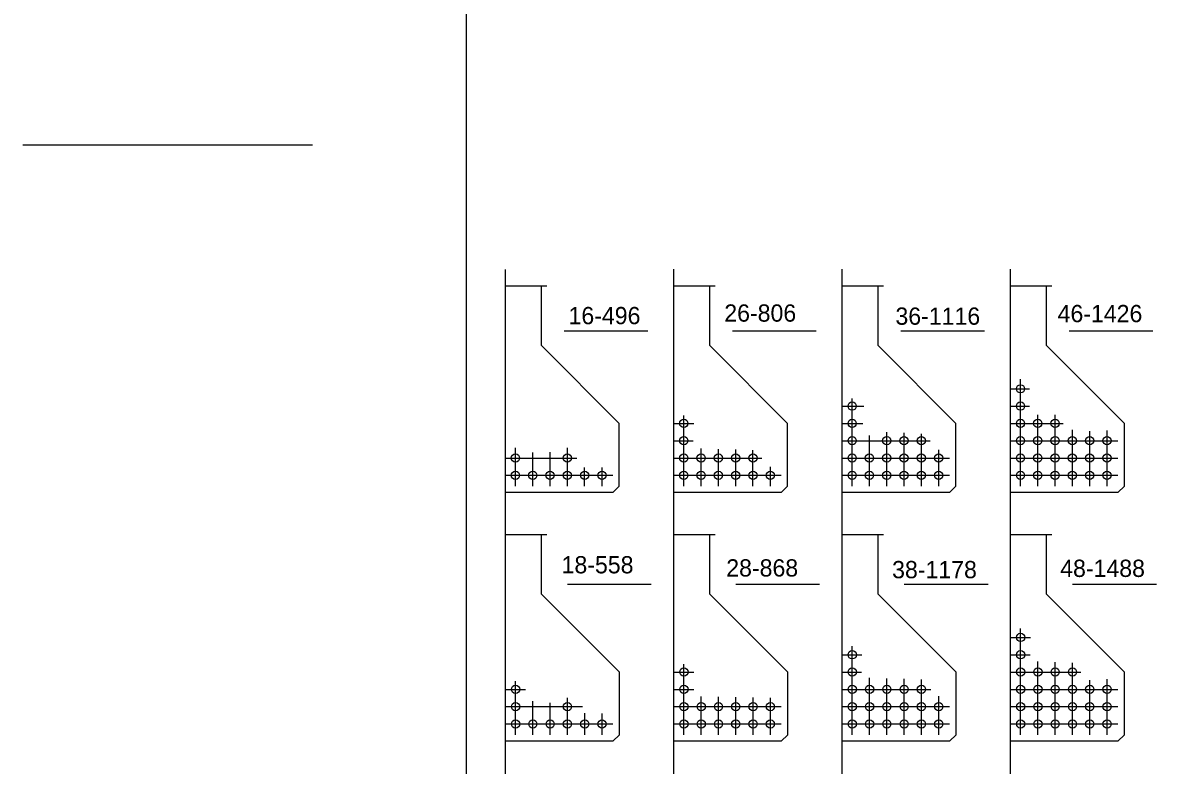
# Model space of a CAD drawing. Extents: x 1005 to 1123, y 2008 to 2074.
# Drawn here: x 1005.42 to 1027.31, y 2029.07 to 2043.4 of the extents above; entities that cross this region are included whole.
import ezdxf

# ---------------------------------------------------------------- set-up
doc = ezdxf.new("R2010")
doc.units = 0
for name, color, linetype in [('Level 1', 7, 'Continuous'), ('Level 37', 7, 'Continuous'), ('Level 8', 7, 'Continuous')]:
    doc.layers.add(name, color=color, linetype=linetype)

msp = doc.modelspace()

# ---------------------------------------------------------------- linework, layer by layer
at = {"layer": 'Level 1'}
msp.add_line((1013.989, 2013.041), (1013.989, 2069.04), dxfattribs=at)
at = {"layer": 'Level 37'}
msp.add_line((1011.017, 2041.04), (1005.42, 2041.04), dxfattribs=at)
at = {"layer": 'Level 8'}
for p, q in [((1014.732, 2038.643), (1014.739, 2014.968)), ((1017.982, 2038.644), (1017.989, 2014.969)), ((1021.232, 2038.645), (1021.239, 2014.97)), ((1024.482, 2038.646), (1024.489, 2014.971)), ((1014.731, 2038.326), (1015.539, 2038.326)), ((1014.767, 2038.326), (1015.539, 2038.326)), ((1015.434, 2037.172), (1015.434, 2038.326)), ((1017.981, 2038.326), (1018.789, 2038.326)), ((1018.017, 2038.326), (1018.789, 2038.326)), ((1018.684, 2037.172), (1018.684, 2038.326)), ((1021.231, 2038.326), (1022.039, 2038.326)), ((1021.267, 2038.326), (1022.039, 2038.326)), ((1021.934, 2037.172), (1021.934, 2038.326)), ((1024.481, 2038.326), (1025.289, 2038.326)), ((1024.517, 2038.326), (1025.289, 2038.326)), ((1025.184, 2037.172), (1025.184, 2038.326)), ((1015.871, 2037.454), (1017.487, 2037.454)), ((1019.121, 2037.454), (1020.737, 2037.454)), ((1019.121, 2037.454), (1020.737, 2037.454)), ((1022.371, 2037.454), (1023.987, 2037.454)), ((1022.371, 2037.454), (1023.987, 2037.454)), ((1022.371, 2037.454), (1023.987, 2037.454)), ((1025.621, 2037.454), (1027.237, 2037.454)), ((1025.621, 2037.454), (1027.237, 2037.454)), ((1025.621, 2037.454), (1027.237, 2037.454)), ((1025.621, 2037.454), (1027.237, 2037.454)), ((1016.938, 2035.669), (1015.434, 2037.172)), ((1020.188, 2035.669), (1018.684, 2037.172)), ((1023.438, 2035.669), (1021.934, 2037.172)), ((1026.688, 2035.669), (1025.184, 2037.172)), ((1024.683, 2034.458), (1024.683, 2036.522)), ((1024.482, 2036.337), (1024.86, 2036.337)), ((1021.433, 2034.458), (1021.433, 2036.149)), ((1021.232, 2036.003), (1021.657, 2036.003)), ((1024.482, 2036.003), (1024.86, 2036.003)), ((1025.018, 2034.458), (1025.018, 2035.836)), ((1025.351, 2034.458), (1025.351, 2035.836)), ((1016.938, 2034.458), (1016.938, 2035.669)), ((1017.982, 2035.669), (1018.377, 2035.669)), ((1018.183, 2034.458), (1018.183, 2035.823)), ((1020.188, 2034.458), (1020.188, 2035.669)), ((1021.232, 2035.669), (1021.641, 2035.669)), ((1023.438, 2034.458), (1023.438, 2035.669)), ((1024.482, 2035.669), (1025.509, 2035.669)), ((1026.688, 2034.458), (1026.688, 2035.669)), ((1021.768, 2034.458), (1021.768, 2035.438)), ((1022.101, 2034.458), (1022.101, 2035.503)), ((1022.435, 2034.458), (1022.435, 2035.486)), ((1022.769, 2034.458), (1022.769, 2035.469)), ((1025.685, 2034.458), (1025.685, 2035.543)), ((1026.019, 2034.458), (1026.019, 2035.519)), ((1026.354, 2034.458), (1026.354, 2035.533)), ((1014.933, 2034.458), (1014.933, 2035.196)), ((1015.935, 2034.458), (1015.935, 2035.196)), ((1017.983, 2035.335), (1018.362, 2035.335)), ((1018.518, 2034.458), (1018.518, 2035.182)), ((1018.851, 2034.458), (1018.851, 2035.172)), ((1021.233, 2035.335), (1022.937, 2035.335)), ((1024.483, 2035.335), (1026.562, 2035.335)), ((1014.733, 2035.001), (1016.118, 2035.001)), ((1015.268, 2034.458), (1015.268, 2035.105)), ((1015.601, 2034.458), (1015.601, 2035.115)), ((1017.983, 2035.001), (1019.691, 2035.001)), ((1019.185, 2034.458), (1019.185, 2035.163)), ((1019.519, 2034.458), (1019.519, 2035.153)), ((1021.233, 2035.001), (1023.312, 2035.001)), ((1023.104, 2034.458), (1023.104, 2035.161)), ((1024.483, 2035.001), (1026.562, 2035.001)), ((1016.269, 2034.458), (1016.269, 2034.817)), ((1016.604, 2034.458), (1016.604, 2034.821)), ((1019.854, 2034.458), (1019.854, 2034.832)), ((1014.733, 2034.667), (1016.812, 2034.667)), ((1017.983, 2034.667), (1020.062, 2034.667)), ((1021.233, 2034.667), (1023.312, 2034.667)), ((1024.483, 2034.667), (1026.562, 2034.667)), ((1016.812, 2034.333), (1014.733, 2034.333)), ((1016.812, 2034.333), (1016.938, 2034.458)), ((1020.062, 2034.333), (1017.983, 2034.333)), ((1020.062, 2034.333), (1020.188, 2034.458)), ((1023.312, 2034.333), (1021.233, 2034.333)), ((1023.312, 2034.333), (1023.438, 2034.458)), ((1026.562, 2034.333), (1024.483, 2034.333)), ((1026.562, 2034.333), (1026.688, 2034.458)), ((1014.733, 2033.526), (1015.541, 2033.526)), ((1014.768, 2033.526), (1015.541, 2033.526)), ((1015.436, 2032.372), (1015.436, 2033.526)), ((1017.983, 2033.526), (1018.791, 2033.526)), ((1018.018, 2033.526), (1018.791, 2033.526)), ((1018.686, 2032.372), (1018.686, 2033.526)), ((1021.233, 2033.526), (1022.041, 2033.526)), ((1021.268, 2033.526), (1022.041, 2033.526)), ((1021.936, 2032.372), (1021.936, 2033.526)), ((1024.483, 2033.526), (1025.291, 2033.526)), ((1024.518, 2033.526), (1025.291, 2033.526)), ((1025.186, 2032.372), (1025.186, 2033.526)), ((1015.94, 2032.568), (1017.556, 2032.568)), ((1019.19, 2032.568), (1020.806, 2032.568)), ((1019.19, 2032.568), (1020.806, 2032.568)), ((1022.44, 2032.568), (1024.056, 2032.568)), ((1022.44, 2032.568), (1024.056, 2032.568)), ((1022.44, 2032.568), (1024.056, 2032.568)), ((1025.69, 2032.568), (1027.306, 2032.568)), ((1025.69, 2032.568), (1027.306, 2032.568)), ((1025.69, 2032.568), (1027.306, 2032.568)), ((1025.69, 2032.568), (1027.306, 2032.568)), ((1016.939, 2030.869), (1015.436, 2032.372)), ((1020.189, 2030.869), (1018.686, 2032.372)), ((1023.439, 2030.869), (1021.936, 2032.372)), ((1026.689, 2030.869), (1025.186, 2032.372)), ((1024.685, 2029.658), (1024.685, 2031.711)), ((1024.484, 2031.537), (1024.879, 2031.537)), ((1021.435, 2029.658), (1021.435, 2031.366)), ((1018.185, 2029.658), (1018.185, 2031.021)), ((1021.234, 2031.203), (1021.621, 2031.203)), ((1024.484, 2031.203), (1024.869, 2031.203)), ((1025.019, 2029.658), (1025.019, 2031.076)), ((1025.353, 2029.658), (1025.353, 2031.063)), ((1025.687, 2029.658), (1025.687, 2031.05)), ((1016.939, 2029.658), (1016.939, 2030.869)), ((1017.984, 2030.869), (1018.374, 2030.869)), ((1020.189, 2029.658), (1020.189, 2030.869)), ((1021.234, 2030.869), (1021.611, 2030.869)), ((1023.439, 2029.658), (1023.439, 2030.869)), ((1024.484, 2030.869), (1025.849, 2030.869)), ((1026.689, 2029.658), (1026.689, 2030.869)), ((1014.935, 2029.658), (1014.935, 2030.694)), ((1021.769, 2029.658), (1021.769, 2030.758)), ((1022.103, 2029.658), (1022.103, 2030.747)), ((1022.437, 2029.658), (1022.437, 2030.735)), ((1022.771, 2029.658), (1022.771, 2030.723)), ((1026.021, 2029.658), (1026.021, 2030.714)), ((1026.355, 2029.658), (1026.355, 2030.733)), ((1014.734, 2030.535), (1015.129, 2030.535)), ((1015.937, 2029.658), (1015.937, 2030.374)), ((1017.984, 2030.535), (1018.374, 2030.535)), ((1018.519, 2029.658), (1018.519, 2030.4)), ((1018.853, 2029.658), (1018.853, 2030.392)), ((1019.187, 2029.658), (1019.187, 2030.385)), ((1019.521, 2029.658), (1019.521, 2030.377)), ((1019.855, 2029.658), (1019.855, 2030.37)), ((1021.234, 2030.535), (1022.954, 2030.535)), ((1023.105, 2029.658), (1023.105, 2030.405)), ((1024.484, 2030.535), (1026.564, 2030.535)), ((1014.734, 2030.201), (1016.229, 2030.201)), ((1015.269, 2029.658), (1015.269, 2030.306)), ((1015.603, 2029.658), (1015.603, 2030.275)), ((1017.984, 2030.201), (1020.064, 2030.201)), ((1021.234, 2030.201), (1023.314, 2030.201)), ((1024.484, 2030.201), (1026.564, 2030.201)), ((1016.271, 2029.658), (1016.271, 2030.078)), ((1016.605, 2029.658), (1016.605, 2030.066)), ((1014.734, 2029.867), (1016.814, 2029.867)), ((1017.984, 2029.867), (1020.064, 2029.867)), ((1021.234, 2029.867), (1023.314, 2029.867)), ((1024.484, 2029.867), (1026.564, 2029.867)), ((1016.814, 2029.533), (1014.734, 2029.533)), ((1016.814, 2029.533), (1016.939, 2029.658)), ((1020.064, 2029.533), (1017.984, 2029.533)), ((1020.064, 2029.533), (1020.189, 2029.658)), ((1023.314, 2029.533), (1021.234, 2029.533)), ((1023.314, 2029.533), (1023.439, 2029.658)), ((1026.564, 2029.533), (1024.484, 2029.533)), ((1026.564, 2029.533), (1026.689, 2029.658))]:
    msp.add_line(p, q, dxfattribs=at)
for centre in [(1024.683, 2036.337), (1021.433, 2036.003), (1024.683, 2036.003), (1018.183, 2035.669), (1021.433, 2035.669), (1024.683, 2035.669), (1025.017, 2035.669), (1025.351, 2035.669), (1018.183, 2035.335), (1021.433, 2035.335), (1022.101, 2035.335), (1022.435, 2035.335), (1022.769, 2035.335), (1024.683, 2035.335), (1025.017, 2035.335), (1025.351, 2035.335), (1025.685, 2035.335), (1026.019, 2035.335), (1026.354, 2035.335), (1014.933, 2035.001), (1015.935, 2035.001), (1018.183, 2035.001), (1018.517, 2035.001), (1018.851, 2035.001), (1019.185, 2035.001), (1019.519, 2035.001), (1021.433, 2035.001), (1021.767, 2035.001), (1022.101, 2035.001), (1022.435, 2035.001), (1022.769, 2035.001), (1023.104, 2035.001), (1024.683, 2035.001), (1025.017, 2035.001), (1025.351, 2035.001), (1025.685, 2035.001), (1026.019, 2035.001), (1026.354, 2035.001), (1014.933, 2034.667), (1015.267, 2034.667), (1015.601, 2034.667), (1015.935, 2034.667), (1016.269, 2034.667), (1016.604, 2034.667), (1018.183, 2034.667), (1018.517, 2034.667), (1018.851, 2034.667), (1019.185, 2034.667), (1019.519, 2034.667), (1019.854, 2034.667), (1021.433, 2034.667), (1021.767, 2034.667), (1022.101, 2034.667), (1022.435, 2034.667), (1022.769, 2034.667), (1023.104, 2034.667), (1024.683, 2034.667), (1025.017, 2034.667), (1025.351, 2034.667), (1025.685, 2034.667), (1026.019, 2034.667), (1026.354, 2034.667), (1024.685, 2031.537), (1021.435, 2031.203), (1024.685, 2031.203), (1018.185, 2030.869), (1021.435, 2030.869), (1024.685, 2030.869), (1025.019, 2030.869), (1025.353, 2030.869), (1025.687, 2030.869), (1014.935, 2030.535), (1018.185, 2030.535), (1021.435, 2030.535), (1021.769, 2030.535), (1022.103, 2030.535), (1022.437, 2030.535), (1022.771, 2030.535), (1024.685, 2030.535), (1025.019, 2030.535), (1025.353, 2030.535), (1025.687, 2030.535), (1026.021, 2030.535), (1026.355, 2030.535), (1014.935, 2030.201), (1015.937, 2030.201), (1018.185, 2030.201), (1018.519, 2030.201), (1018.853, 2030.201), (1019.187, 2030.201), (1019.521, 2030.201), (1019.855, 2030.201), (1021.435, 2030.201), (1021.769, 2030.201), (1022.103, 2030.201), (1022.437, 2030.201), (1022.771, 2030.201), (1023.105, 2030.201), (1024.685, 2030.201), (1025.019, 2030.201), (1025.353, 2030.201), (1025.687, 2030.201), (1026.021, 2030.201), (1026.355, 2030.201), (1014.935, 2029.867), (1015.269, 2029.867), (1015.603, 2029.867), (1015.937, 2029.867), (1016.271, 2029.867), (1016.605, 2029.867), (1018.185, 2029.867), (1018.519, 2029.867), (1018.853, 2029.867), (1019.187, 2029.867), (1019.521, 2029.867), (1019.855, 2029.867), (1021.435, 2029.867), (1021.769, 2029.867), (1022.103, 2029.867), (1022.437, 2029.867), (1022.771, 2029.867), (1023.105, 2029.867), (1024.685, 2029.867), (1025.019, 2029.867), (1025.353, 2029.867), (1025.687, 2029.867), (1026.021, 2029.867), (1026.355, 2029.867)]:
    msp.add_circle(centre, 0.0797, dxfattribs=at)

# ---------------------------------------------------------------- texts
for s, p in [('16-496 ', (1015.958, 2037.584)), ('26-806 ', (1018.965, 2037.633)), ('36-1116', (1022.269, 2037.573)), ('46-1426', (1025.4, 2037.623)), ('18-558 ', (1015.824, 2032.774)), ('28-868 ', (1019.003, 2032.713)), ('38-1178', (1022.205, 2032.68)), ('48-1488', (1025.45, 2032.705))]:
    msp.add_text(s, height=0.3333, dxfattribs=at).set_placement(p)

doc.saveas('drawing.dxf')
